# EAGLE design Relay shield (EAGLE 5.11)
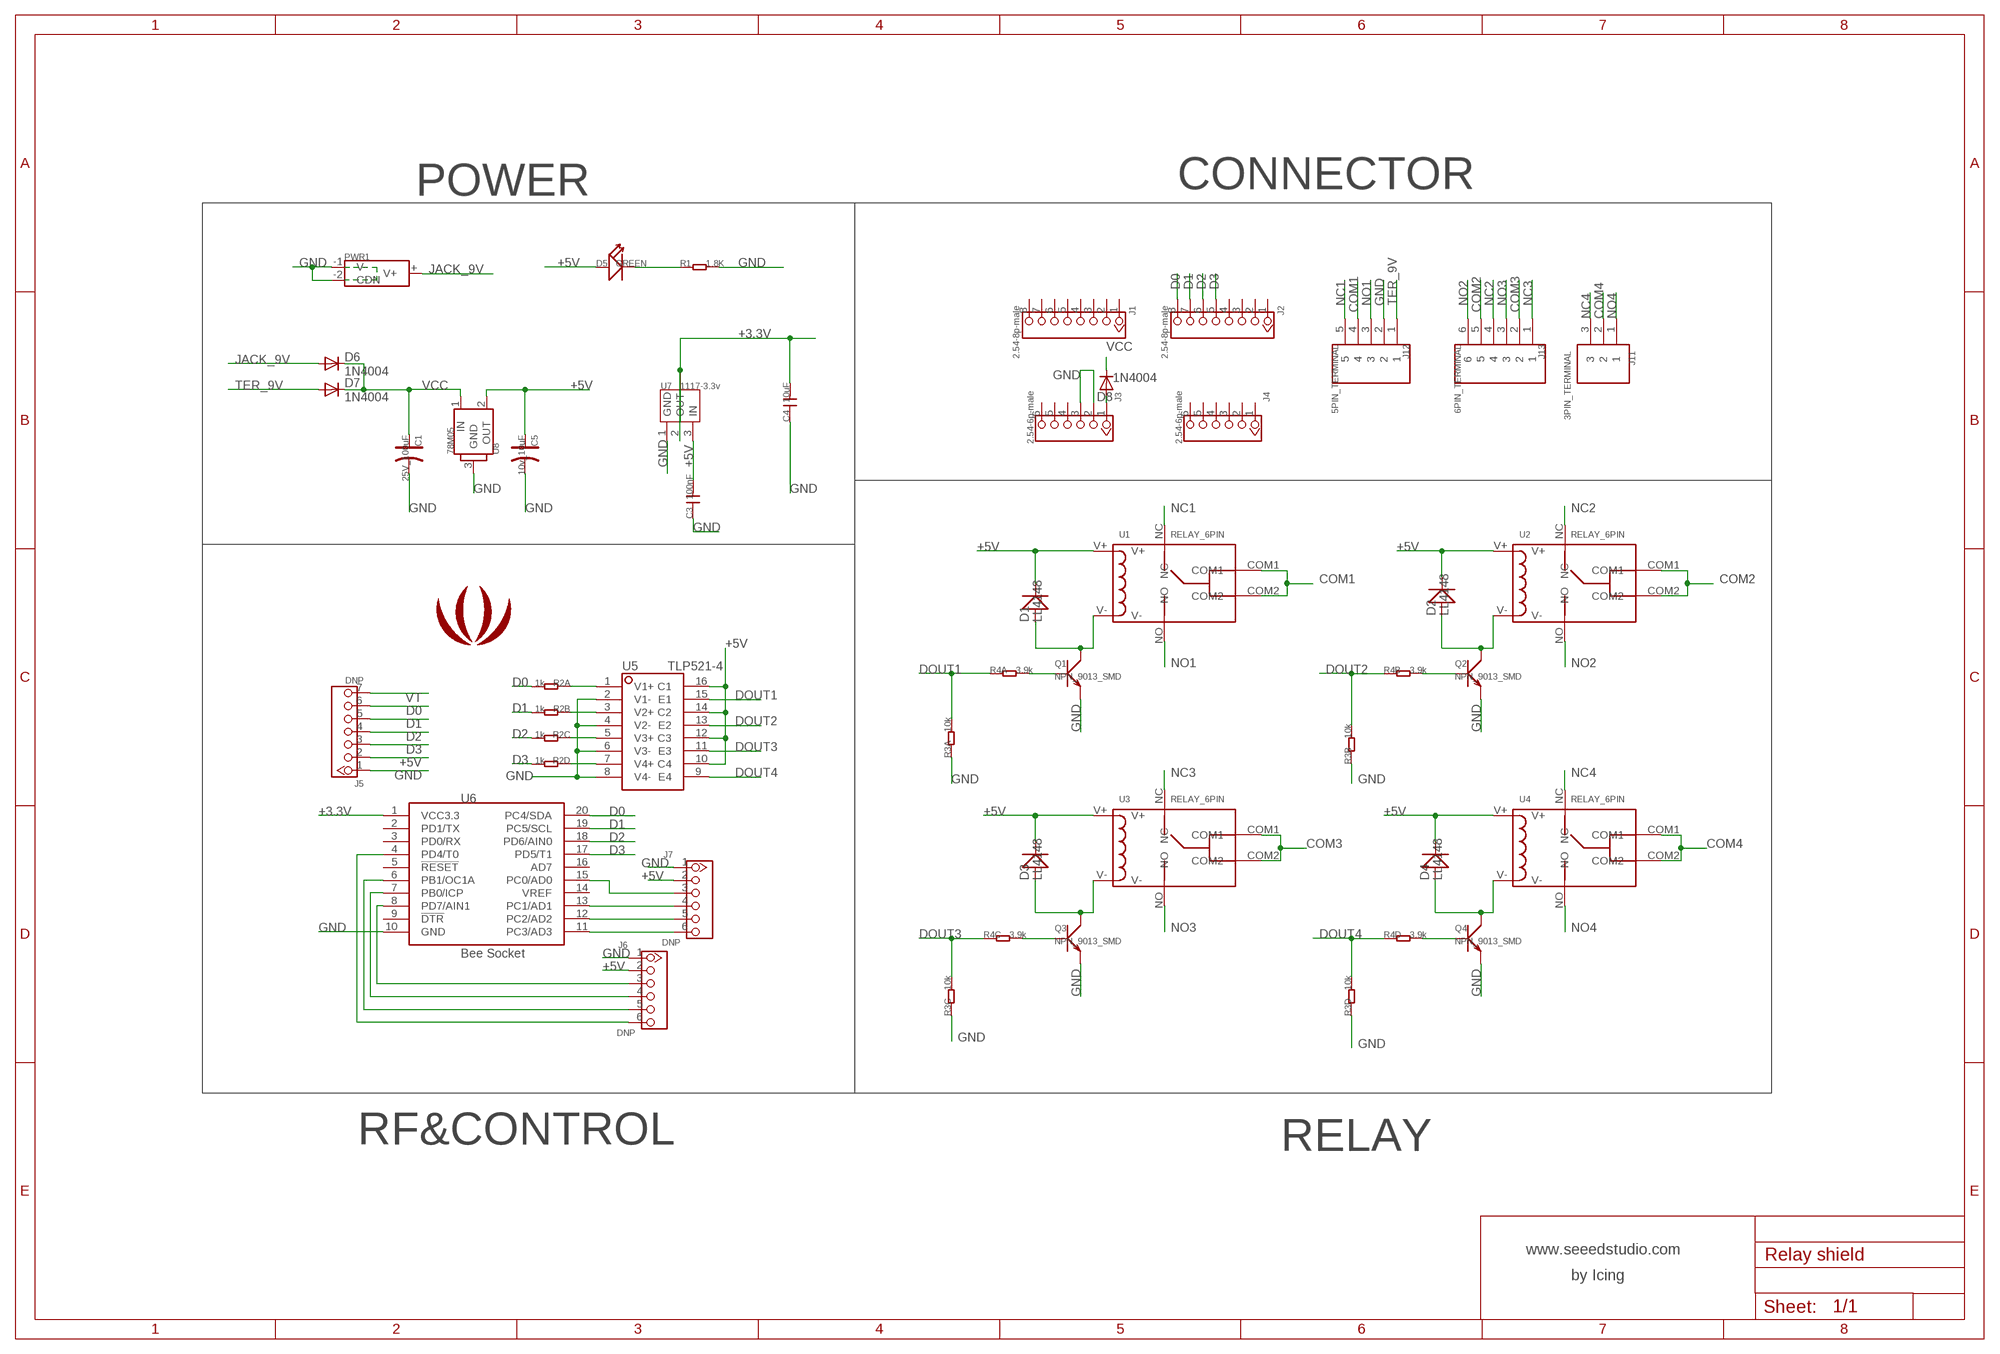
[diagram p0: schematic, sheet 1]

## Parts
C1  25V_100uF  CAP-ELECTRO-C  [ELECTRO-SMD-C-6MM]
C3  100nF  C-0603  [0603]
C4  10uF  C-0805  [0805]
C5  10v_10uF  CAP-AVX-B  [AVX-B]
D1  LL4148  D-1206  [D1206]
D2  LL4148  D-1206  [D1206]
D3  LL4148  D-1206  [D1206]
D4  LL4148  D-1206  [D1206]
D5  GREEN  LED'0603'  [LED-0603]
D6  1N4004  DIODESMA  [SMA-DIODE]
D7  1N4004  DIODESMA  [SMA-DIODE]
D8  1N4004  DIODESMA  [SMA-DIODE]
J1  2.54-8p-male  CK_1X8DD  [CK_1X8]
J2  2.54-8p-male  CK_1X8DD  [CK_1X8]
J3  2.54-6p-male  CK_1X6  [CK_1X6]
J4  2.54-6p-male  CK_1X6  [CK_1X6]
J5  DNP  CK_1X7  [CK_1X7]
J6  DNP  CK_1X6  [CK_1X6]
J7  DNP  CK_1X6  [CK_1X6]
J11  3PIN_TERMINAL  [3PIN_TERMINAL]
J12  5PIN_TERMINAL  [5PIN_TERMINAL]
J13  6PIN_TERMINAL  [6PIN_TERMINAL]
LOGO1  LOGO_SILK  [LOGO_SILK]
PWR1  JACK-3P-2.5MM-2.5MM  [PW-3P-2.5]
Q1  NPN_9013_SMD  TRANSISTOR-NPN-SOT23''  [SOT23]
Q2  NPN_9013_SMD  TRANSISTOR-NPN-SOT23''  [SOT23]
Q3  NPN_9013_SMD  TRANSISTOR-NPN-SOT23''  [SOT23]
Q4  NPN_9013_SMD  TRANSISTOR-NPN-SOT23''  [SOT23]
R1  1.8K  R-0603  [0603]
R2  1k  R-4R-1206  [1206-8-3.3X2.4]
R3  10k  R-4R-1206  [1206-8-3.3X2.4]
R4  3.9k  R-4R-1206  [1206-8-3.3X2.4]
U1  RELAY_6PIN  [RELAY_6PIN]
U2  RELAY_6PIN  [RELAY_6PIN]
U3  RELAY_6PIN  [RELAY_6PIN]
U4  RELAY_6PIN  [RELAY_6PIN]
U5  TLP521-4  [TLP521-4]
U6  Bee Socket  CCBEE_PRO  [CCBEE-PRO]
U7  1117-3.3v  LD1117SOT89  [SOT89]
U8  78M05  78M05-TO252  [TO252]

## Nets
+3.3V: C4.2 U6.1(VCC3.3) U7.2(OUT) U7.4(TAB)
+5V: C3.2 C5.+ D1.- D2.- D3.- D4.- D5.+ J5.2 J6.2 J7.2 U1.V+ U2.V+ U3.V+ U4.V+ U5.10(C4) U5.12(C3) U5.14(C2) U5.16(C1) U7.3(IN) U8.2(OUT)
COM1: J12.4 U1.COM1 U1.COM2
COM2: J13.5 U2.COM1 U2.COM2
COM3: J13.2 U3.COM1 U3.COM2
COM4: J11.2 U4.COM1 U4.COM2
D0: J2.8 J5.6 R2.8 U6.20(PC4/SDA)
D1: J2.7 J5.5 R2.7 U6.19(PC5/SCL)
D2: J2.6 J5.4 R2.6 U6.18(PD6/AIN0)
D3: J2.5 J5.3 R2.5 U6.17(PD5/T1)
DOUT1: R3.8 R4.1 U5.15(E1)
DOUT2: R3.7 R4.2 U5.13(E2)
DOUT3: R3.6 R4.3 U5.11(E3)
DOUT4: R3.5 R4.4 U5.9(E4)
GND: C1.- C3.1 C4.1 C5.- J3.2 J3.3 J5.1 J6.1 J7.1 J12.2 PWR1.-1(V-) PWR1.-2(CDN) Q1.2(E) Q2.2(E) Q3.2(E) Q4.2(E) R1.2 R3.1 R3.2 R3.3 R3.4 U5.2(V1-) U5.4(V2-) U5.6(V3-) U5.8(V4-) U6.10(GND) U7.1(GND) U8.3(GND)
JACK_9V: D6.A PWR1.+(V+)
N$1: J7.3 U6.15(PC0/AD0)
N$2: J7.4 U6.13(PC1/AD1)
N$3: R2.1 U5.1(V1+)
N$4: J7.5 U6.12(PC2/AD2)
N$5: D8.A J3.1
N$6: Q4.1(B) R4.5
N$7: D1.+ Q1.3(C) U1.V-
N$8: J7.6 U6.11(PC3/AD3)
N$11: Q3.1(B) R4.6
N$12: D2.+ Q2.3(C) U2.V-
N$13: R2.2 U5.3(V2+)
N$15: R2.3 U5.5(V3+)
N$17: Q2.1(B) R4.7
N$18: D3.+ Q3.3(C) U3.V-
N$20: R2.4 U5.7(V4+)
N$23: Q1.1(B) R4.8
N$24: D4.+ Q4.3(C) U4.V-
N$25: D5.- R1.1
N$31: J6.6 U6.4(PD4/T0)
N$34: J6.3 U6.8(PD7/AIN1)
N$35: J6.4 U6.7(PB0/ICP)
N$36: J6.5 U6.6(PB1/OC1A)
NC1: J12.5 U1.NC
NC2: J13.4 U2.NC
NC3: J13.1 U3.NC
NC4: J11.3 U4.NC
NO1: J12.3 U1.NO
NO2: J13.6 U2.NO
NO3: J13.3 U3.NO
NO4: J11.1 U4.NO
TER_9V: D7.A J12.1
VCC: C1.+ D6.C D7.C D8.C U8.1(IN)
VT: J5.7
Unconnected: J1.1 J1.2 J1.3 J1.4 J1.5 J1.6 J1.7 J1.8 J2.1 J2.2 J2.3 J2.4 J3.4 J3.5 J3.6 J4.1 J4.2 J4.3 J4.4 J4.5 J4.6 U6.2(PD1/TX) U6.3(PD0/RX) U6.5(!RESET) U6.9(!DTR) U6.14(VREF) U6.16(AD7)

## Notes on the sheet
- POWER | CONNECTOR
- RF&CONTROL | RELAY
- www.seeedstudio.com
- by Icing

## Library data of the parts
C1 C5 = Discrete:CAP*: Electrolytic Capacitors,Tantalum Capacitors and Super Capacitors
C3 C4 = Discrete:C*: Ceramic Capacitors
D1-D4 = Discrete:D*
D5 = Discrete:LED*
D6-D8 = SparkFun:DIODE: Diode
J1 J2 = CONNECTER1:CK_1X8
J3 J4 J6 J7 = CONNECTER:CK_1X6
J5 = CONNECTER:CK_1X7
J11 = Seeed:3PIN_TERMINAL
J12 = Seeed:5PIN_TERMINAL
J13 = Seeed:6PIN_TERMINAL
LOGO1 = logo:LOGO_SILK
PWR1 = Connector:JACK-3P-2.5MM
Q1-Q4 = Discrete:TRANSISTOR-NPN*: NPN audion
R1 = Discrete:R*
R2-R4 = Discrete:R-4R*: Resistor Array
U1-U4 = Seeed:RELAY_6PIN
U5 = Seeed:TLP521-4
U6 = EXT_moudle:CCBEE
U7 = IC:LD1117
U8 = IC:78M05: http://search.digikey.com/scripts/DkSearch/dksus.dll?Detail&name=MC78M05CDTXTR-ND

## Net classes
0 default: width 0.152 mm, drill 0.305 mm, clearance 0.152 mm

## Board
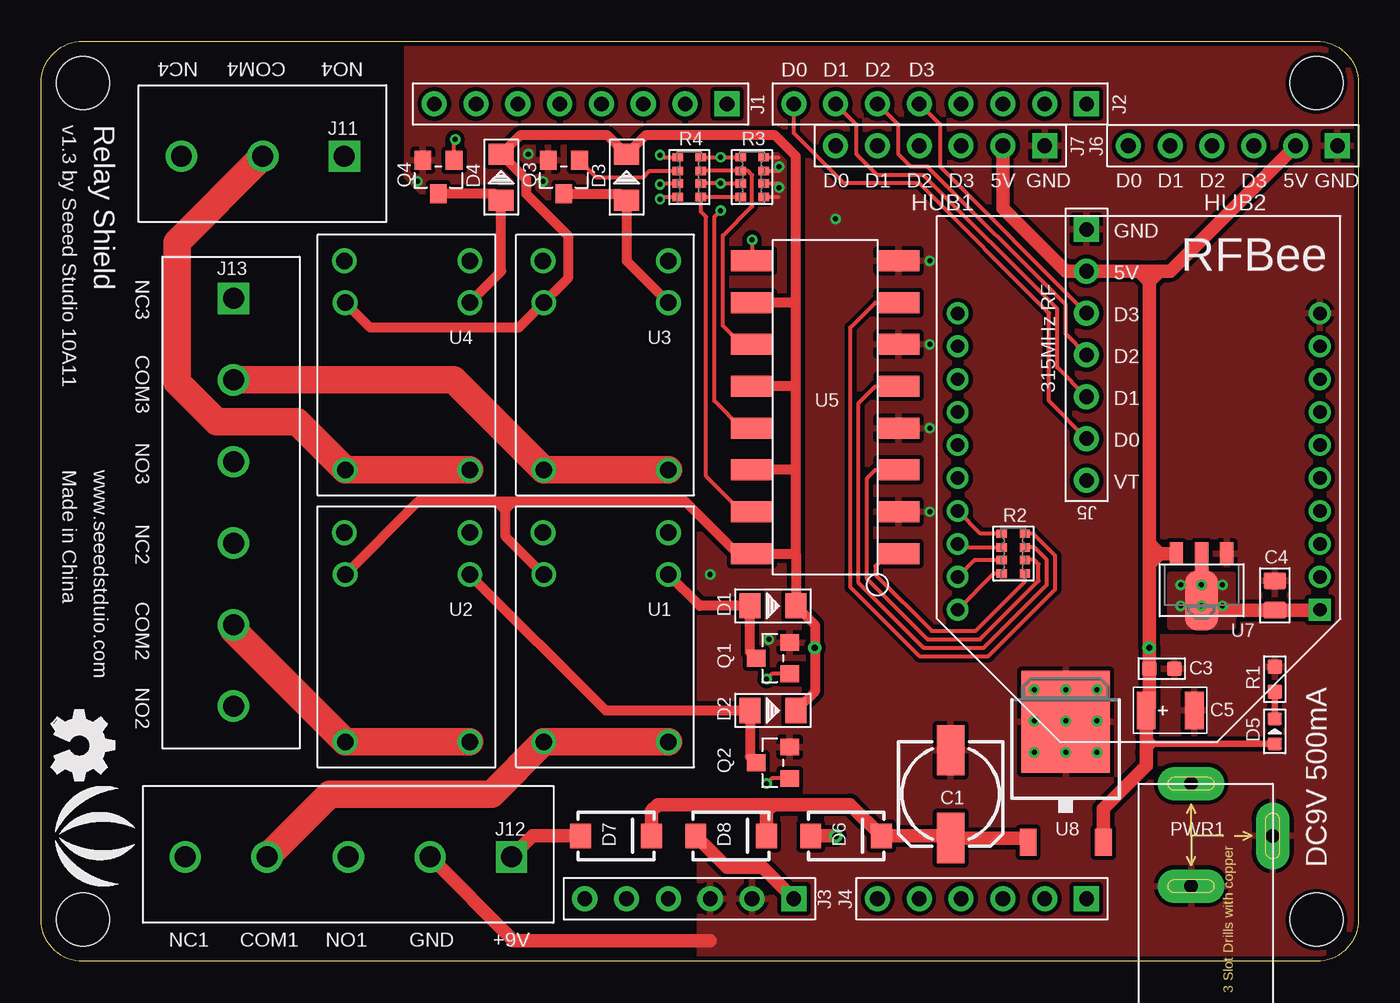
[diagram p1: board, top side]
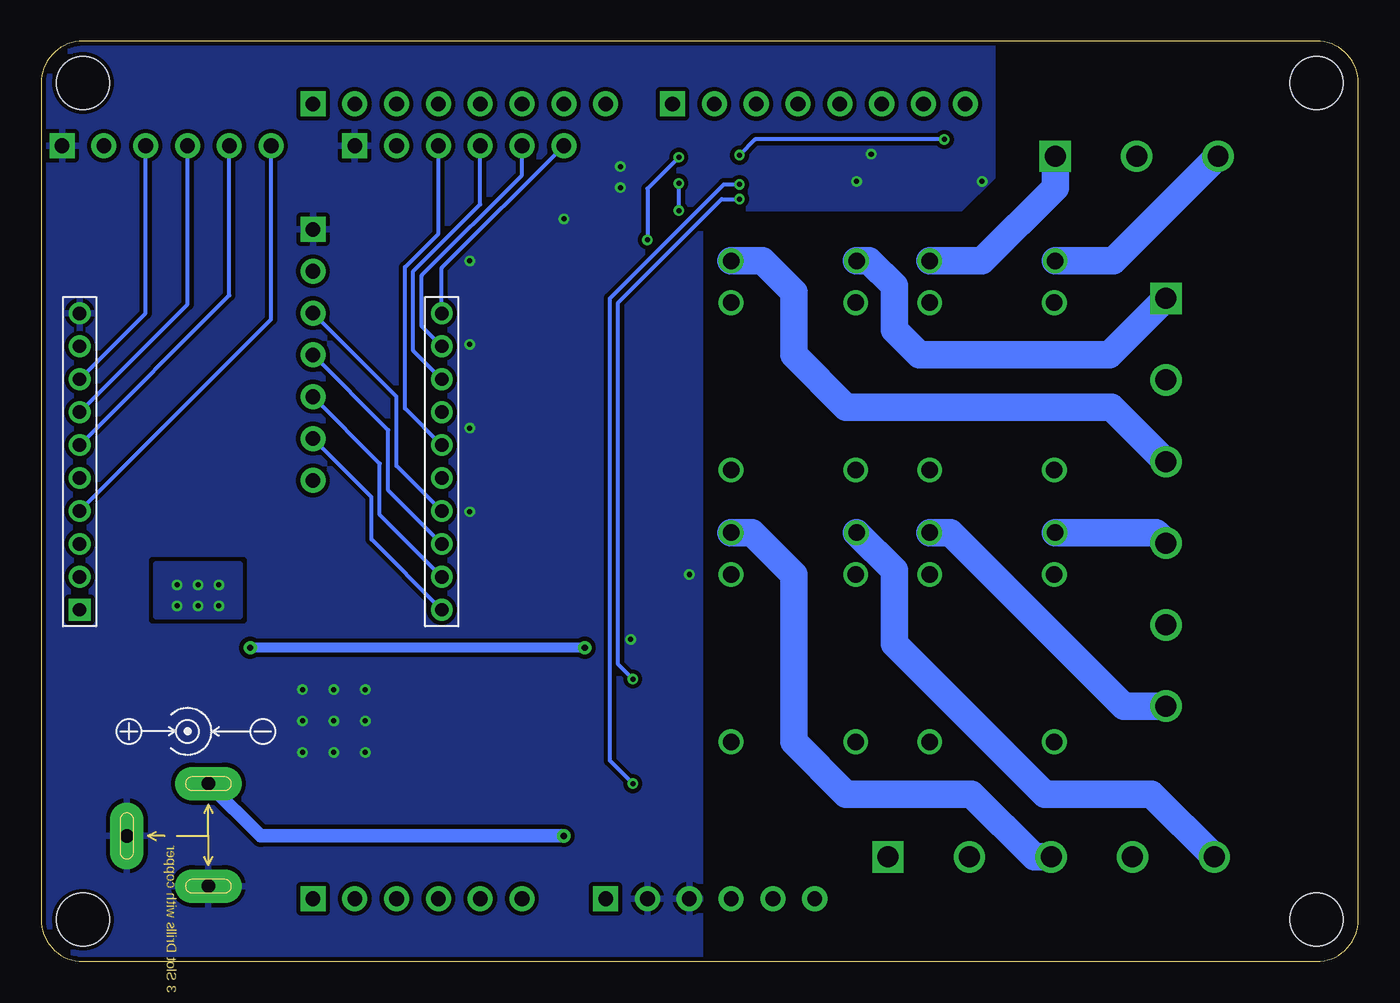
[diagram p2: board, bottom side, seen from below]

Size 80.01 x 55.88 mm. Coordinates in mm from the lower left corner, seen from the top.
Outline: 2.54,55.88 77.47,55.88 arc-90 80.01,53.34 80.01,2.54 arc-90 77.47,0 2.54,0 arc-90 0,2.54 0,53.34 arc-90 2.54,55.88
Copper layers (1*16): Top 0.035mm / dielectric 1.5mm / Bottom 0.035mm
Design rules "SeeedStudio_rule_no_angle_090911 *": minimum track width 6mil, minimum drill 12mil, track to track 6mil, track to pad 6mil, pad to pad 6mil, via to via 6mil, smd to smd 0mil, copper to edge 10mil, drill to drill 10mil, minimum pad ring 10mil, minimum via ring 6mil, stop-mask expansion 2mil, vias tented up to drill 100mil, thermal gap 10mil
Holes 3.2 mm at 77.47,53.34 2.54,53.34 2.54,2.54 77.47,2.54
tRestrict: area 43.6,46.1 to 44.2,49.1

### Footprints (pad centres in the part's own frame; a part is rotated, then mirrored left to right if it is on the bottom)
ELECTRO-SMD-C-6MM = smd 3.048 x 1.651: + 2.667,0; - -2.667,0
0603 = smd 0.889 x 0.889: 1 -0.762,0; 2 0.762,0
0805 = smd 1.016 x 1.397: 1 -0.889,0; 2 0.889,0
AVX-B = smd 1.143 x 2.286: + -1.46,0; - 1.46,0
D1206 = smd 1.27 x 1.524: + -1.397,0; - 1.397,0
LED-0603 = smd 0.762 x 0.889: + -0.762,0; - 0.762,0
SMA-DIODE = smd 1.27 x 1.47: A -2.15,0; C 2.15,0
CK_1X8 = drill 0.889 pad 1.524 square: 1 0,8.89 | drill 0.889 pad 1.524 round: 2 0,6.35; 3 0,3.81; 4 0,1.27; 5 0,-1.27; 6 0,-3.81; 7 0,-6.35; 8 0,-8.89
CK_1X6 = drill 0.889 pad 1.524 square: 1 0,6.35 | drill 0.889 pad 1.524 round: 2 0,3.81; 3 0,1.27; 4 0,-1.27; 5 0,-3.81; 6 0,-6.35
CK_1X7 = drill 0.889 pad 1.524 square: 1 0,8.89 | drill 0.889 pad 1.524 round: 2 0,6.35; 3 0,3.81; 4 0,1.27; 5 0,-1.27; 6 0,-3.81; 7 0,-6.35
3PIN_TERMINAL = drill 1.27 pad 1.778 square: 1 0,0 | drill 1.27 pad 1.778 round: 2 0,4.95; 3 0,9.893
5PIN_TERMINAL = drill 1.27 pad 1.778 square: 1 0,0 | drill 1.27 pad 1.778 round: 2 0,4.95; 3 0,9.919; 4 0,14.856; 5 0,19.825
6PIN_TERMINAL = drill 1.27 pad 1.778 square: 1 0,0 | drill 1.27 pad 1.778 round: 2 0,4.95; 3 0,9.919; 4 0,14.856; 5 0,19.825; 6 0,24.752
PW-3P-2.5 = drill 0.813 pad 2.032 long: + 3.175,0; -1 -3.048,0; -2 0,-4.953
SOT23 = smd 1.016 x 1.143: 1 -0.95,-1.016; 2 0.95,-1.016; 3 0,1.016
1206-8-3.3X2.4 = smd 0.508 x 0.635: 1 -1.206,-0.699; 2 -0.381,-0.699; 3 0.381,-0.699; 4 1.206,-0.699; 5 1.206,0.699; 6 0.381,0.699; 7 -0.381,0.699; 8 -1.206,0.699
RELAY_6PIN = drill 1 round: COM1 -10.16,7.569; COM2 -10.16,0; NC 2.54,7.62; NO 2.54,0; V+ 0,7.569; V- 0,0
TLP521-4 = smd 2.54 x 1.27: 1 -4.445,8.89; 2 -4.445,6.35; 3 -4.445,3.81; 4 -4.445,1.27; 5 -4.445,-1.27; 6 -4.445,-3.81; 7 -4.445,-6.35; 8 -4.445,-8.89; 9 4.445,-8.89; 10 4.445,-6.35; 11 4.445,-3.81; 12 4.445,-1.27; 13 4.445,1.27; 14 4.445,3.81; 15 4.445,6.35; 16 4.445,8.89
CCBEE-PRO = drill 0.813 square: 1 -11,9 | drill 0.813 round: 2 -11,7; 3 -11,5; 4 -11,3; 5 -11,1; 6 -11,-1; 7 -11,-3; 8 -11,-5; 9 -11,-7; 10 -11,-9; 11 11,-9; 12 11,-7; 13 11,-5; 14 11,-3; 15 11,-1; 16 11,1; 17 11,3; 18 11,5; 19 11,7; 20 11,9
SOT89 = smd 0.8 x 1.4: 1 -1.524,-1.905; 3 1.524,-1.905 | smd 0.8 x 1.9: 2 0,-1.651 | smd 2.032 x 3.65: 4 0,0.94
TO252 = smd 1.016 x 1.651: 1 -2.286,-4.826; 2 2.286,-4.826 | smd 5.4 x 6.2: 3 0,2.5

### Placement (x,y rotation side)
C1  55.24,10.16 270 top
C3  68.07,17.78 180 top
C4  74.93,22.23 270 top
C5  68.58,15.24 0 top
D1  44.45,21.59 0 top
D2  44.45,15.24 0 top
D3  35.56,47.62 90 top
D4  27.94,47.62 90 top
D5  74.93,13.97 90 top
D6  48.9,7.62 0 top
D7  34.93,7.62 0 top
D8  41.91,7.62 0 top
J1  32.77,52.07 270 top
J2  54.61,52.07 270 top
J3  39.37,3.81 270 top
J4  57.15,3.81 270 top
J5  63.5,35.56 0 top
J6  72.39,49.53 270 top
J7  54.61,49.53 270 top
J11  18.41,48.89 90 top
J12  28.57,6.35 90 top
J13  11.68,40.26 180 top
LOGO1  2.54,7.62 270 top
PWR1  69.85,7.62 90 top
Q1  44.45,18.41 90 top
Q2  44.45,12.07 90 top
Q3  31.75,47.62 180 top
Q4  24.13,47.62 180 top
R1  74.93,17.14 90 top
R2  59.05,24.77 90 top
R3  43.18,47.62 90 top
R4  39.37,47.62 90 top
U1  38.1,23.5 90 top
U2  26.04,23.5 90 top
U3  38.1,40 90 top
U4  26.04,40 90 top
U5  47.62,33.65 180 top
U6  66.67,30.35 180 top
U7  70.48,22.86 180 top
U8  62.23,12.07 0 top
U$2  [OSHW_FILLX150_NOTEXT]  0.63,15.24 270 top

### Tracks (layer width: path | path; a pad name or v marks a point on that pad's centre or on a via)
+3.3V  (via drill 0.3 pad 0.64)
  Top 0.813: U7.2 v70.48,22.86 U7.4 71.07,21.34 C4.2 77.66,21.34 U6.1
  other vias: 71.75,22.86 69.21,22.86 69.21,21.59 70.48,21.59 71.75,21.59
  pour Bottom (isolate 0.254): 67.94,24.13 73.02,24.13 73.02,20.96 67.94,20.96
  pour Top (isolate 0.254, no thermals): 68.58,23.5 72.39,23.5 72.39,20.32 68.58,20.32
+5V  (via drill 0.38 pad 0.81)
  Top 0.406: 67.63,13.21 D5.+ | 67.12,13.72 67.63,13.21 | 67.12,12.7 67.63,13.21
  Top 0.61: U4.V+ 19.99,38.48 29.01,38.48 U3.V+ 32,41.48 32,44.07 29.46,46.61 29.46,47.5 D4.- 29.08,50.16 34.42,50.16 D3.- 36.7,50.16 44.58,50.16 45.85,48.89 45.85,40 | 45.85,24.77 D1.- 46.99,20.45 v46.99,19.05 46.99,16.38 D2.- | 45.85,24.77 45.85,29.84 | 45.85,29.84 45.85,34.92 | 45.85,34.92 45.85,40 | 45.85,40 U5.10 | 45.85,34.92 U5.12 | 45.85,29.84 U5.14 | 45.85,24.77 U5.16 42.29,24.77 39.12,27.94 28.7,27.94 | U2.V+ 22.91,27.94 27.69,27.94 | 27.69,27.94 28.7,27.94 | U1.V+ 28.19,25.83 28.19,27.43 | 27.69,27.94 28.19,27.43 | 28.7,27.94 28.19,27.43
  Top 0.813: U8.2 64.52,9.27 67.12,11.88 67.12,12.7 67.12,13.72 C5.+ 67.31,15.43 C3.2 v67.31,19.05 67.31,24.13 | J7.2 58.42,45.72 62.23,41.91 J5.2 66.67,41.91 | J6.2 68.58,41.91 67.94,41.91 | 66.67,41.91 67.94,41.91 | 67.31,24.13 67.31,25.4 | 67.31,25.4 67.31,41.27 | 67.31,41.27 66.67,41.91 | 67.31,41.27 67.94,41.91 | 67.94,24.77 U7.3 | 67.31,25.4 67.94,24.77 | 67.31,24.13 67.94,24.77
  Bottom 0.61: v46.99,19.05 v67.31,19.05
COM1
  Top 1.676: U1.COM2 U1.COM1 27.36,10.16 17.53,10.16 J12.4
COM2
  Top 1.676: U2.COM2 U2.COM1 11.68,20.12 J13.5
COM3
  Top 1.676: U3.COM2 U3.COM1 25.07,35.31 J13.2
COM4
  Top 1.676: J11.2 8.25,43.68 8.25,35.18 10.67,32.77 15.55,32.77 U4.COM1 U4.COM2
D0
  Top 0.254: R2.8 57.88,23.56 U6.20 | J5.6 61.21,34.04 61.21,39.37 53.34,47.24 48.77,47.24 45.72,50.29 J2.8
  Bottom 0.254: J5.6 59.94,28.19 59.94,25.62 U6.20
D1
  Top 0.254: R2.7 56.71,24.38 U6.19 | J5.5 61.72,36.07 61.72,39.62 53.59,47.75 50.8,47.75 49.53,49.02 49.53,50.8 J2.7
  Bottom 0.254: J5.5 59.44,30.23 59.44,27.11 U6.19
D2
  Top 0.254: R2.6 55.88,25.15 U6.18 | J5.4 62.23,38.1 62.23,39.88 53.85,48.26 52.83,48.26 52.07,49.02 52.07,50.8 J2.6
  Bottom 0.254: J5.4 58.93,32.26 58.93,28.61 U6.18
D3
  Top 0.254: R2.5 57.06,25.97 U6.17 | J5.3 54.61,48.26 54.61,50.8 J2.5
  Bottom 0.254: J5.3 58.42,34.29 58.42,30.1 U6.17
DOUT1
  Top 0.254: U5.15 42.55,27.3 40.39,29.46 40.39,45.21 40.07,45.53 R4.1 R3.8
DOUT2  (via drill 0.3 pad 0.64)
  Top 0.254: R4.2 v41.27,47.24 R3.7 | U5.13 42.55,32.38 40.89,34.04 40.89,45.21 v41.27,45.59
  Bottom 0.254: v41.27,45.59 v41.27,47.24
DOUT3
  Top 0.254: U5.11 42.55,37.46 41.4,38.61 41.4,44.07 43.18,45.85 43.18,47.75 42.93,48.01 R3.6 R4.3
DOUT4  (via drill 0.3 pad 0.64)
  Top 0.254: R3.5 v41.27,48.83 R4.4 | v43.18,43.81 U5.9
  Bottom 0.254: v43.18,43.81 43.18,46.93 v41.27,48.83
GND  (via drill 0.3 pad 0.64)
  Top 0.254: R3.1 44.77,46.42 | R3.2 44.83,47.24 | R3.3 44.83,48.01 | R3.4 44.77,48.83
  Top 0.813: J12.2 28.71,1.27 40.64,1.27
  other vias: 29.59,49.02 30.48,47.37 22.86,47.37 48.26,45.08 53.98,37.46 53.98,27.3 53.98,42.54 53.98,32.38 44.83,48.26 44.83,46.99 44.2,19.56 40.64,23.5 62.23,12.7 62.23,14.61 62.23,16.51 60.33,16.51 60.33,14.61 60.33,12.7 64.13,12.7 64.13,14.61 64.13,16.51
  pour Bottom: -6.99,54.61 -5.71,54.61 -5.71,53.34 -6.99,53.34
  pour Top (isolate 0.254, rank 6): 22.23,55.88 80.01,55.88 80.01,0 40.01,0 40.01,45.72 24.13,45.72 22.23,47.62
  pour Bottom (isolate 0.254, rank 6): 22.23,55.88 80.01,55.88 80.01,0 40.01,0 40.01,45.72 24.13,45.72 22.23,47.62
JACK_9V  (via drill 0.38 pad 0.81)
  Top 0.813: D6.A v48.26,7.62
  Bottom 0.813: PWR1.+ 66.67,7.62 v48.26,7.62
N$1
  Bottom 0.254: J7.3 55.88,44.2 57.91,42.16 57.91,33.59 U6.15
N$2
  Bottom 0.254: J7.4 53.34,45.97 57.4,41.91 57.4,37.08 U6.13
N$3
  Top 0.254: R2.1 59.75,23.05 56.77,20.07 54.1,20.07 50.67,23.5 50.67,24 51.44,24.77 U5.1
N$4
  Bottom 0.254: J7.5 50.8,47.75 56.9,41.66 56.9,38.57 U6.12
N$5
  Top 0.813: J3.1 43.81,5.71 41.66,5.71 D8.A
N$6  (via drill 0.3 pad 0.64)
  Top 0.254: R4.5 37.72,48.83 v37.59,48.96 | v25.15,49.91 25.08,49.84 Q4.1
  Bottom 0.254: v25.15,49.91 36.64,49.91 v37.59,48.96
N$7
  Top 0.61: U1.V- 40.01,21.59 D1.+ 43.05,18.8 Q1.3
N$8
  Bottom 0.254: J7.6 55.68,42.11 U6.11
N$11
  Top 0.254: R4.6 36.96,48.01 36.58,47.62 33.72,47.62 Q3.1
N$12
  Top 0.61: U2.V- 34.29,15.24 D2.+ 43.05,12.45 Q2.3
N$13
  Top 0.254: R2.2 60.33,24.38 60.58,24.13 60.58,23.11 57.02,19.56 53.85,19.56 50.16,23.24 50.16,29.34 50.67,29.84 U5.3
N$15
  Top 0.254: R2.3 60.33,25.15 61.09,24.38 61.09,22.86 57.28,19.05 53.59,19.05 49.66,22.99 49.66,33.91 50.67,34.92 U5.5
N$17  (via drill 0.3 pad 0.64)
  Top 0.254: R4.7 37.66,47.24 v37.59,47.18 | v44.07,10.79 44.39,11.12 Q2.1
  Bottom 0.254: v37.59,47.18 38.54,47.18 45.47,40.26 45.47,12.19 v44.07,10.79
N$18
  Top 0.61: Q3.3 35.18,46.61 D3.+ 35.56,42.54 U3.V-
N$20
  Top 0.254: R2.4 60.26,25.97 61.6,24.64 61.6,22.61 57.53,18.54 53.34,18.54 49.15,22.73 49.15,38.48 50.67,40 U5.7
N$23  (via drill 0.3 pad 0.64)
  Top 0.254: R4.8 37.72,46.42 v37.59,46.29 | Q1.1 44.39,17.46 v44.07,17.14
  Bottom 0.254: v37.59,46.29 38.67,46.29 44.96,40 44.96,18.03 v44.07,17.14
N$24
  Top 0.61: Q4.3 27.56,46.61 D4.+ 27.94,41.91 U4.V-
N$25
  Top 0.406: D5.- R1.1
N$31
  Bottom 0.254: J6.6 66.04,38.99 U6.4
N$34
  Bottom 0.254: J6.3 73.66,39.37 U6.8
N$35
  Bottom 0.254: J6.4 71.12,39.91 U6.7
N$36
  Bottom 0.254: J6.5 68.58,40.45 U6.6
NC1
  Bottom 1.676: U1.NC 28.19,23.75 28.19,19.3 19.05,10.16 12.56,10.16 J12.5
NC2
  Bottom 1.676: U2.NC 12.32,26.04 J13.4
NC3
  Bottom 1.676: U3.NC 29.72,42.54 28.19,41.02 28.19,38.35 26.67,36.83 15.11,36.83 J13.1
NC4
  Bottom 1.676: U4.NC 14.87,42.54 J11.3
NO1
  Bottom 1.676: U1.NO 36.83,26.04 34.29,23.5 34.29,13.34 31.12,10.16 23.5,10.16 19.69,6.35 J12.3
NO2
  Bottom 1.676: U2.NO 24.77,26.04 14.24,15.51 J13.6
NO3
  Bottom 1.676: J13.3 15,33.65 31.12,33.65 34.29,36.83 34.29,40.64 36.2,42.54 U3.NO
NO4
  Bottom 1.676: U4.NO 22.86,42.54 18.41,46.99 J11.1
TER_9V
  Top 0.813: J12.1 29.84,7.62 D7.A
VCC
  Top 0.813: D7.C 37.08,9.13 37.47,9.53 43.69,9.53 | 44.06,9.13 D8.C | 44.45,9.53 44.06,9.13 | 44.45,9.53 49.14,9.53 D6.C 55.12,7.62 C1.+ 59.69,7.49 U8.1 | 44.06,9.13 44.06,9.15 43.69,9.53 | 43.69,9.53 44.45,9.53

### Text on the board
tPlace: NC4 | COM4 | NO4 | D0 | D1 | D2 | D3 | v1.3 by Seeed Studio 10A11 | Relay Shield | D0 | D1 | D2 | D3 | 5V | GND | D0 | D1 | D2 | D3 | 5V | GND | HUB1 | HUB2 | GND | NC3 | 5V | RFBee | D3 | COM3 | D2 | 315MHz RF | D1 | NO3 | D0 | Made in China | www.seeedstduio.com | VT | NC2 | COM2 | NO2 | DC9V 500mA | NC1 | COM1 | NO1 | GND | +9V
